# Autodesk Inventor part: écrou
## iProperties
Shininess: 78.0
Length Units: 11269
Angle Units: 11279
Time Units: 11290
Mass Units: 11283
Length Display Precision: 3
Angle Display Precision: 2
Created: 2002-06
Part Number: écrou
Material: Par défaut
Document SubType Name: Modélisation
Designer: REVEST Pierre
Density: 0.0
Volumn: 0.0
Area: 0.0
PropertySet Name: Model Information
Control State: 0
Master: False
Checked Out: False
Author: REVEST Pierre
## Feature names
1. Extrusion1
2. Extrusion2
3. Extrusion3
4. Chanfrein1 [Chamfer]
5. Perçage1 [Hole]
